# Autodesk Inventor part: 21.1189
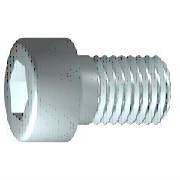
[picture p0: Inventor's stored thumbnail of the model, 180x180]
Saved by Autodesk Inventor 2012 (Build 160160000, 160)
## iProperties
Created: 2006-02
Part Number: 21.1189
Material: Steel, Mild
Description: M8X25 POWER-LOCK SCREW
Document SubType Name: Modeling
Standard: DIN 7984
Designer: Andy Moles
Standards Organization: DIN
Language: en-US
Size Designation: M8 x 25
Categories: <MemberInstance><Categories><Category DisplayName="Fasteners" InternalName="e4da775c-781d-43d5-af7c-5136215cf5a6" Mnemonic="FSTN"><Category DisplayName="Bolts"
Density: 7.86 g/cm^3
Mass: 13.063 g
Surface Area: 10.8236 cm^2
Volume: 1.66196 cm^3
Author: Andy Moles
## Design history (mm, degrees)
body "Solid1"
revolve "Body" stored, may be unused: angle "d10" = 90 deg
sketch "Sketch2"
  geometry: L1 (0, -9.38)-(0, 9.38) reference; L2 (-9.38, 0)-(9.38, 0) reference; L3 (2.887, 0)-(1.443, -2.5); L4 (1.443, -2.5)-(-1.443, -2.5); L5 (-1.443, -2.5)-(-2.887, 0); L6 (-2.887, 0)-(-1.443, 2.5); L7 (-1.443, 2.5)-(1.443, 2.5); L8 (1.443, 2.5)-(2.887, 0); 2 further points
  constraints: 12 end point, 1 coincident, 1 horizontal alignment, 1 point on line, 12 other
extrude "Slot" join sketch "Sketch2" stored distance "d11" = 10; taper "d12" = 0 deg
workplane "Work Plane1"
feature "Thread" dims "d13" = 24 (= GEL), "d14" = 0
chamfer "Chamfer1" distance "d15" = 0.76681 (= -0.5 x SPD + 0.5 x GD); stored, may be unused: second distance "d16" = 0.76681 (= GUL), angle "d27" = 45 deg
sketch "Sketch1"
  geometry: L1 (1.167, 0)-(25, 0); L2 (25, 0)-(25, 4); L3 (25, 4)-(1, 4); L4 (1, 4)-(0.233, 4); L5 (0.233, 4)-(0, 4); L6 (0, 4)-(0, 6.7); L7 (0, 6.7)-(-0.8, 6.7); L8 (-4.3, 3.2)-(-4.3, 2.887); L9 (-4.3, 2.887)-(-0.5, 2.887); L10 (-0.5, 2.887)-(1.167, 0); L11 (-11.03, 0)-(31.005, 0) reference; L12 (0, -1.485)-(0, 8.91) reference; L13 (1, 4)-(0, 4); A1 r 3.5 centre (-0.8, 3.2) between (-0.8, 6.7) and (-4.3, 3.2); 1 further point
  constraints: 22 end point, 6 parallel, 3 point on line, 2 collinear, 2 perpendicular, 2 point on circle, 2 tangent, 1 centre point, 1 horizontal
  dimensions: "d1" = 24 distance from line of L3.end L2 (= GEL); "d2" = 0.76691 distance of L4.end L3.end (computed from GAL); "d5" = 60 deg angle of L10 L1; "d6" = 8 diameter of L3 L1 (= GD); "d7" = 8 diameter of L5 L1 (= BDM); "d8" = 5.7735 diameter of L9 L1 (= 1.1547 x SW); "d26" = 25 distance between parallel lines of L12 L2 (= NLG); "d30" = 3.8 distance of L8.end L9.end; "d31" = 3.5 radius of A1; "d32" = 4.3 distance from line of L6 L8.end; "d33" = 13.4 diameter of L7 L1
other parameters: "GD" = 8 (= NND) [user parameter; used in 2 equation terms], "NLG" = 25 [user parameter; used in 1 equation term], "GEL" = 24 [user parameter; used in 2 equation terms], "KOD" = 13 [user parameter], "KOH" = 5 [user parameter], "INTI" = 3.8 [user parameter], "GAL" = 0.76681 (= 0.61345 x PTC) [user parameter; used in 1 equation term], "GUL" = 0.76681 (= 0.61345 x PTC) [user parameter; used in 1 equation term], "BDM" = 8 (= NND) [user parameter; used in 1 equation term], "SW" = 5 [user parameter; used in 2 equation terms], "RR" = 0.8 [user parameter], "SPD" = 6.46637 (= NND - 1.2269 x PTC) [user parameter; used in 1 equation term], "d19" = 0, "d28" = 0, "d29" = 0, "TOA" = 30 deg [user parameter], "GD1" = 6.46637 (= THREADDIA - 1.2269 x PTC) [user parameter], "THREADDIA" = 8 [user parameter; used in 1 equation term], "FAWI" = 45 deg [user parameter], "ANG" = 120 deg [user parameter], "TPU" = 8 (computed from PTC) [user parameter], "PTC" = 1.25 [user parameter; used in 5 equation terms], "NND" = 8 [user parameter; used in 3 equation terms], "E0" = 5.775 (= 1.155 x SW) [user parameter]
